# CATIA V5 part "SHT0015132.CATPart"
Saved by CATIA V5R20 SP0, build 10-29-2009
Part number: Part7
Bounding box of the stored display mesh (mm): x 125.5 to 161, y -42 to 42, z 10 to 28
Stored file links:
  E:\张磊\转盘自研\外发冻结数据图纸\3D\最新3D-20230510\2D\2022.11.18-单件图纸\SHT0015132-气动转盘解锁安装钣金\SHT0015132.CATPart
  SHT0015132.CATPart
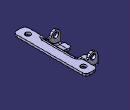
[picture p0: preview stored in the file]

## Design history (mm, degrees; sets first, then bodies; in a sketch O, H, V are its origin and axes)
Body1 (main body)
Body2 "气动转盘解锁安装钣金"
  Solid1: solid without history
Body3 "气动转盘解锁安装钣金"
  Solid2: solid without history
Body4 "更改后"
  Solid3: solid without history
